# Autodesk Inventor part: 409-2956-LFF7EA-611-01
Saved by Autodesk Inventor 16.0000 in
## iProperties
Created: 2010-06
Part Number: 409-2956-LFF7EA-611-01
Cost Center: 0 lbmass
Material: A36 STEEL PLATE
Document SubType Name: Sheet Metal
Designer: S. Boerckel
Authority: 0 in^3
Mass: 69382.5 g
Surface Area: 9922.78 cm^2
Volume: 8827.3 cm^3
Density: 7.86 g/cm^3
Sheet Metal Rule: 3/4"Thk
Description: PUMP MOUNT PLATE
Flat Pattern Width: 38.1 cm
Flat Pattern Length: 121.92 cm
Flat Pattern Area: 4645.15 cm^2
Sheet Metal Width: 47.0000 in
Sheet Metal Length: 752.0000 in^2
User Status: BURN/DRILL
SaveDate: 2008-01-15
SaveTime: 10:24
FileName: Sheet Metal
Wide: =<Flat Pattern Width>cm
Length: =<Flat Pattern Length>cm
Thickness: 0.7500 in
SMR: =<Sheet Metal Rule> - <Material>
Author: S. Boerckel
Revision Number: 0
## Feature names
1. Hole1
2. Plate1
